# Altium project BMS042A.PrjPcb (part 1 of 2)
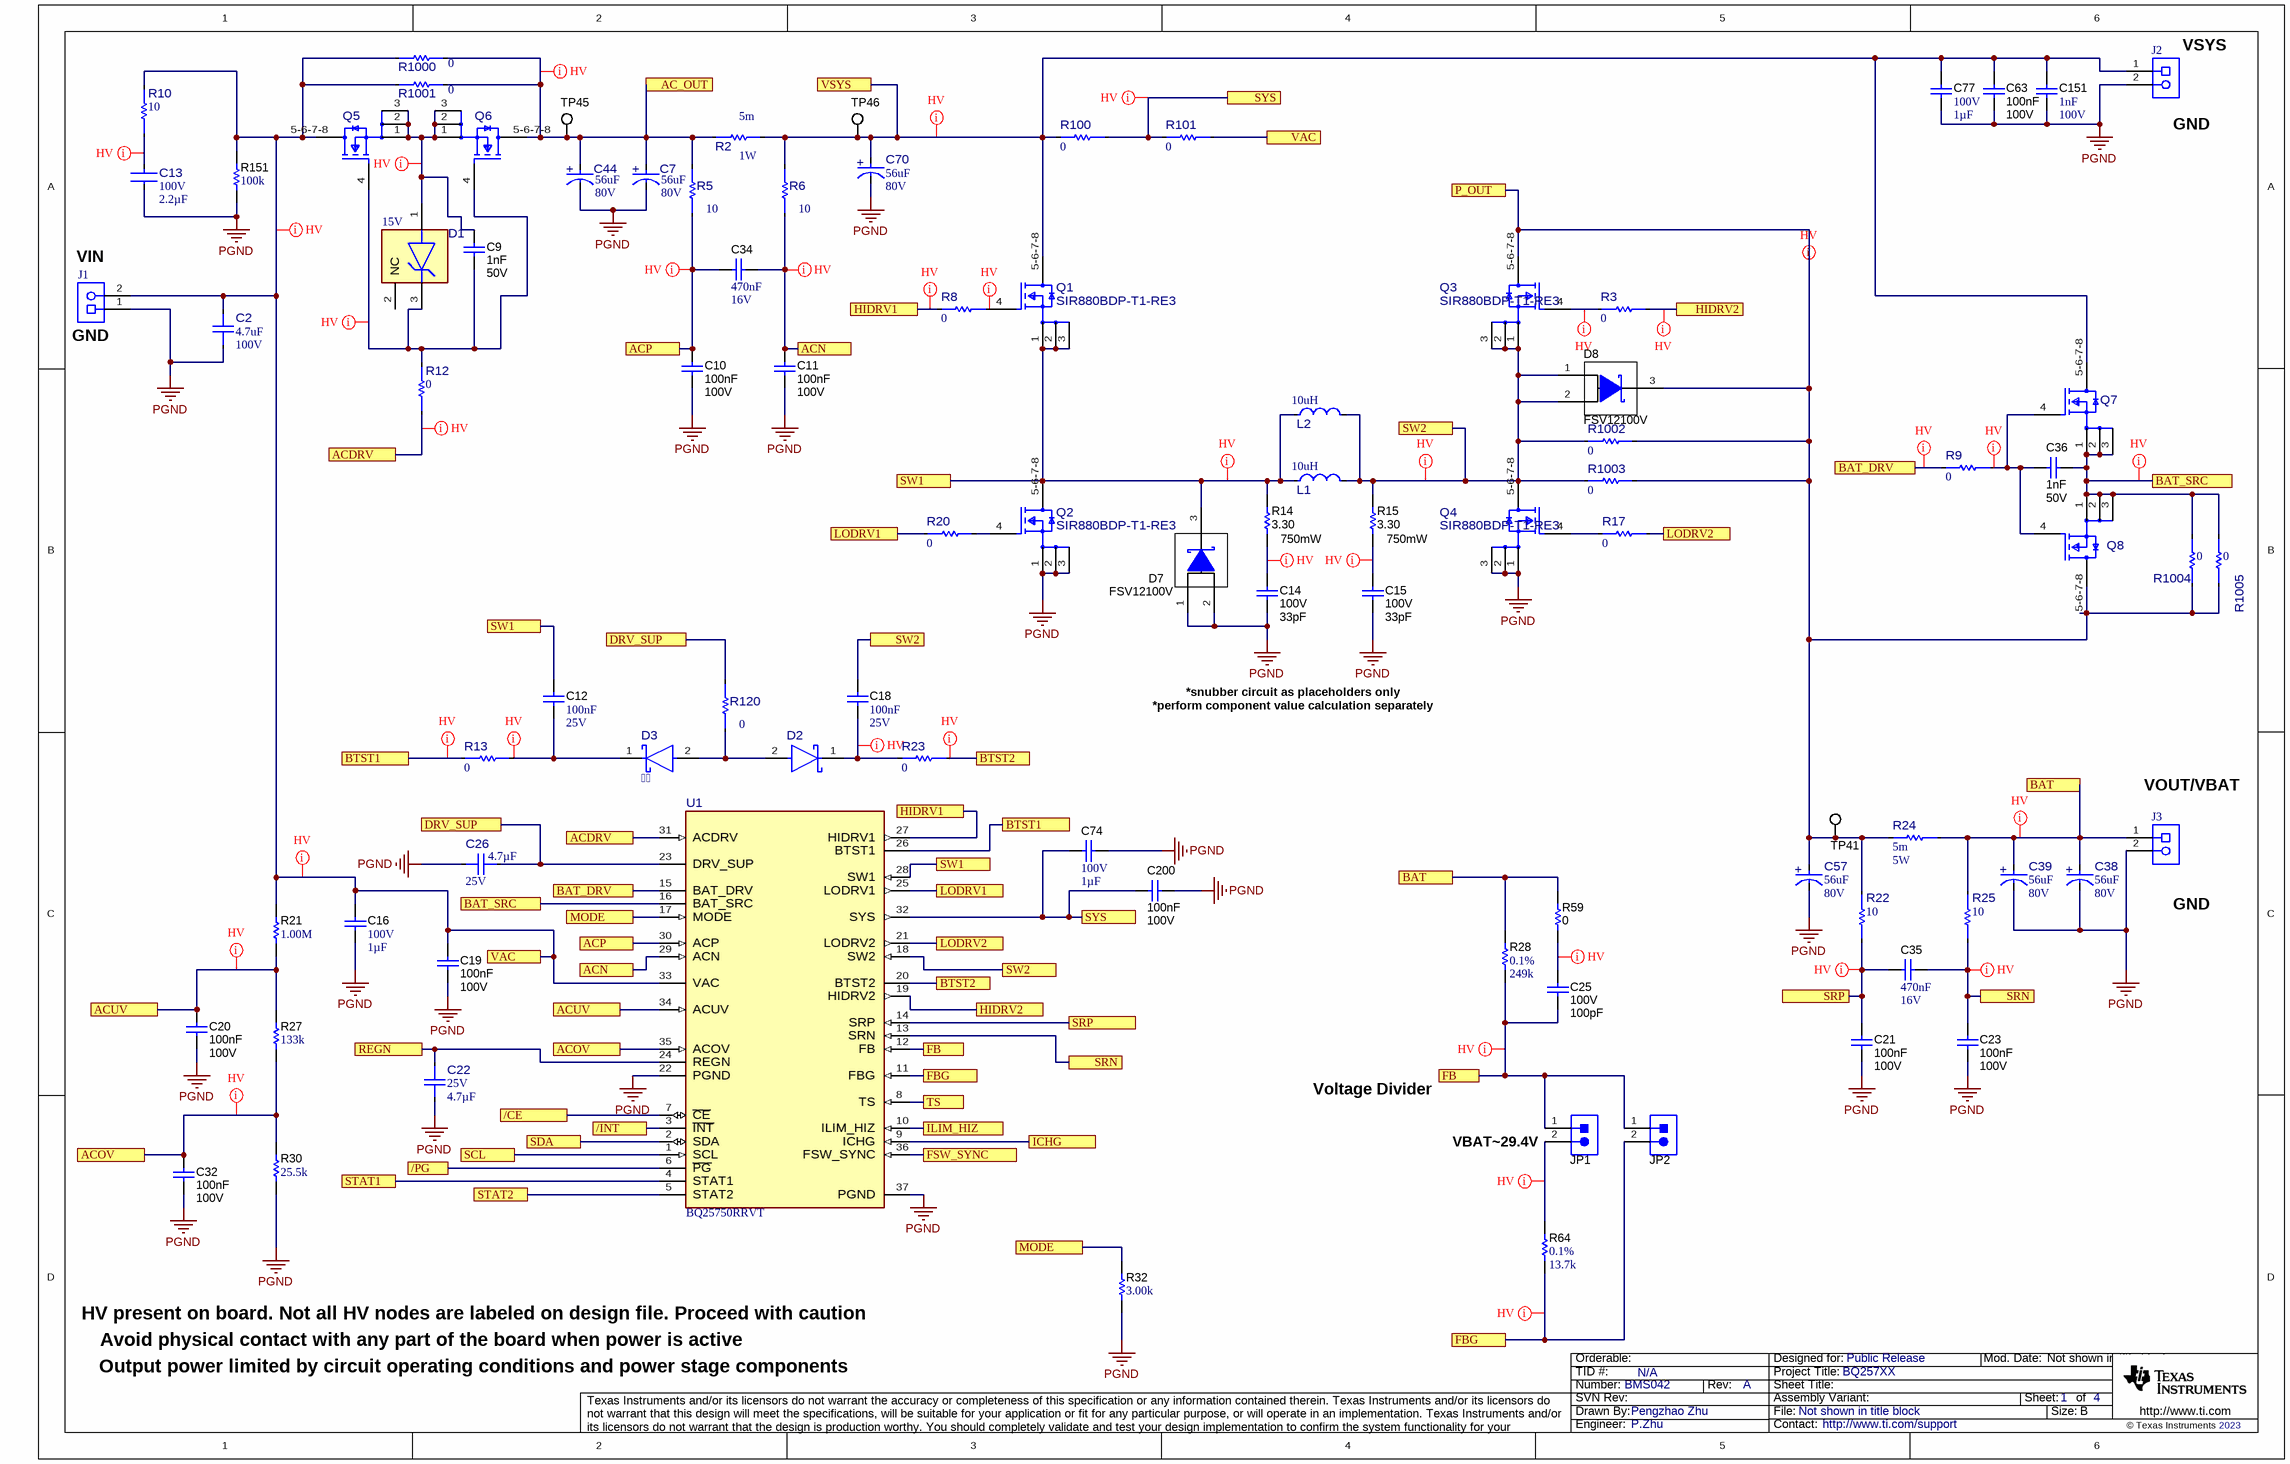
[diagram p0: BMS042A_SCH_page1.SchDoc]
CopyrightYear: 2023; DrawnBy: Pengzhao Zhu; PCB_Layout: P.Zhu; PCB_Rev: A; PRJ_Customer: Public Release; PRJ_Engineer: P.Zhu; PRJ_Number: BMS042; PRJ_Title: BQ257XX; SCH_Rev: A; TechSupport: http://www.ti.com/support; TID: N/A
4 sheets, 274 parts. Net scope: flat (ports and power ports of the same name join across sheets).
Board file: BMS042A_PCB.PcbDoc
Sheets:
  BMS042A_SCH_page1.SchDoc
  BMS042A_SCH_page2.SchDoc
  BMS042A_SCH_powerpath_capacitors.SchDoc
  BMS042A_SCH_Hardware.SchDoc

## Sheet BMS042A_SCH_page1.SchDoc
size 431 x 279 mm; Date: Not shown in title block; ApprovedBy: Not shown in title block; CheckedBy: Not shown in title block; Author: Not shown in title block; CompanyName: Not shown in title block; DrawnBy: Pengzhao Zhu; Engineer: Not shown in title block; Organization: Not shown in title block; Address1: Not shown in title block; Address2: Not shown in title block; Address3: Not shown in title block; Address4: Not shown in title block; DocumentNumber: 1; Revision: Use project parameter SCH_Rev; SheetNumber: 1; SheetTotal: 4; PageSetup: Record=PageOptions¦CenterHorizontal=True¦CenterVertical=True¦PrintScale=1.00¦XCorrection=1.00¦YCorrection=1.00¦PrintKind=0¦BorderSize=5000000¦LeftOffset=0¦BottomOffset=0¦Orientation=2¦PaperLength=1000¦PaperWidth=1000¦Scale=100¦PaperSource=15¦PrintQuality=600¦MediaType=1¦DitherType=10¦PaperKind=Letter¦PrintScaleMode=1

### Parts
C2  ValueDisplayed: 4.7uF  VDC_V: 100V  [FP-GCJ32DC72A475KE01L_1210-MFG]  (hidden comment: GCJ32DC72A475KE01L)
C7  ValueDisplayed: 56uF  VDC_V: 80V  [FP-80SXV56M_SMT_CAP_10MM3_10MM3-MFG]  (hidden comment: 80SXV56M)
C9  Cap_F: 1nF  VDC_V: 50V  [0603_HV]  (hidden comment: C0603C102J5RACTU)
C10  Cap_F: 100nF  VDC_V: 100V  [0603_HV]  (hidden comment: HMK107B7104KAHT)
C11  Cap_F: 100nF  VDC_V: 100V  [0603_HV]  (hidden comment: HMK107B7104KAHT)
C12  Cap_F: 100nF  VDC_V: 25V  [0603_HV]  (hidden comment: 06033C104KAT2A)
C13  VDC_V: 100V  Cap_F: 2.2µF  [FP-CGA6N3X7R2A225K230AE_1210-MFG]  (hidden comment: CGA6N3X7R2A225K230AE)
C14  VDC_V: 100V  ValueDisplayed: 33pF  [0603_HV]  (hidden comment: 06031A330JAT2A)
C15  VDC_V: 100V  ValueDisplayed: 33pF  [0603_HV]  (hidden comment: 06031A330JAT2A)
C16  VDC_V: 100V  Cap_F: 1µF  [0805_150]  (hidden comment: 08051C105K4Z2A)
C18  Cap_F: 100nF  VDC_V: 25V  [0603_HV]  (hidden comment: 06033C104KAT2A)
C19  Cap_F: 100nF  VDC_V: 100V  [0603_HV]  (hidden comment: HMK107B7104KAHT)
C20  Cap_F: 100nF  VDC_V: 100V  [0603_HV]  (hidden comment: HMK107B7104KAHT)
C21  Cap_F: 100nF  VDC_V: 100V  [0603_HV]  (hidden comment: HMK107B7104KAHT)
C22  VDC_V: 25V  Cap_F: 4.7µF  [FP-CGA4J1X7R1E475K125AE_0805-MFG]  (hidden comment: CGA4J1X7R1E475K125AE)
C23  Cap_F: 100nF  VDC_V: 100V  [0603_HV]  (hidden comment: HMK107B7104KAHT)
C25  VDC_V: 100V  ValueDisplayed: 100pF  [0603_HV]  (hidden comment: GCM1885C2A101JA16D)
C26  VDC_V: 25V  Cap_F: 4.7µF  [FP-CGA4J1X7R1E475K125AE_0805-MFG]  (hidden comment: CGA4J1X7R1E475K125AE)
C32  Cap_F: 100nF  VDC_V: 100V  [0603_HV]  (hidden comment: HMK107B7104KAHT)
C34  Cap_F: 470nF  VDC_V: 16V  [0603]  (hidden comment: C0603C474K4RACTU)
C35  Cap_F: 470nF  VDC_V: 16V  [0603]  (hidden comment: C0603C474K4RACTU)
C36  Cap_F: 1nF  VDC_V: 50V  [0603_HV]  (hidden comment: C0603C102J5RACTU)
C38  ValueDisplayed: 56uF  VDC_V: 80V  [FP-80SXV56M_SMT_CAP_10MM3_10MM3-MFG]  (hidden comment: 80SXV56M)
C39  ValueDisplayed: 56uF  VDC_V: 80V  [FP-80SXV56M_SMT_CAP_10MM3_10MM3-MFG]  (hidden comment: 80SXV56M)
C44  ValueDisplayed: 56uF  VDC_V: 80V  [FP-80SXV56M_SMT_CAP_10MM3_10MM3-MFG]  (hidden comment: 80SXV56M)
C57  ValueDisplayed: 56uF  VDC_V: 80V  [FP-80SXV56M_SMT_CAP_10MM3_10MM3-MFG]  (hidden comment: 80SXV56M)
C63  Cap_F: 100nF  VDC_V: 100V  [0603L]  (hidden comment: HMK107B7104KAHT)
C70  ValueDisplayed: 56uF  VDC_V: 80V  [FP-80SXV56M_SMT_CAP_10MM3_10MM3-MFG]  (hidden comment: 80SXV56M)
C74  VDC_V: 100V  Cap_F: 1µF  [0805_150]  (hidden comment: 08051C105K4Z2A)
C77  VDC_V: 100V  Cap_F: 1µF  [0805_150]  (hidden comment: 08051C105K4Z2A)
C151  Cap_F: 1nF  VDC_V: 100V  [0603]  (hidden comment: CGA3E2X7R2A102K080AA)
C200  Cap_F: 100nF  VDC_V: 100V  [0603_HV]  (hidden comment: HMK107B7104KAHT)
D1  Vz_V: 15V  [FP-SZBZX84C15LT3G_SOT23-MFG]
D2  (no value)  [FP-V1FM10-M3-H_DO-219AB-MFG]
D3    [FP-V1FM10-M3-H_DO-219AB-MFG]
D7  FSV12100V  [TO-277A]
D8  FSV12100V  [TO-277A]
J1  (no value)  [FP-TB005-762-02BE_TERM_CONN-MFG]
J2  (no value)  [FP-TB005-762-02BE_TERM_CONN-MFG]
J3  (no value)  [FP-TB005-762-02BE_TERM_CONN-MFG]
JP1  PEC02SAAN  [CONN_PEC02SAAN]  (value not drawn)
JP2  PEC02SAAN  [CONN_PEC02SAAN]  (value not drawn)
L1  value 10uH  [FP-IHLP6767GZER100M01_SMT_INDUCTOR_17MM15_17MM15-MFG]  (hidden comment: IHLP6767GZER100M01)
L2  value 10uH  [FP-CMLB135T-100MS_SMT2_13MM45_12Mm6-MFG]  (hidden comment: CMLB135T-100MS)
Q1  SIR880BDP-T1-RE3  [FP-SIR880BDP-T1-RE3_SO-8-MFG]
Q2  SIR880BDP-T1-RE3  [FP-SIR880BDP-T1-RE3_SO-8-MFG]
Q3  SIR880BDP-T1-RE3  [FP-SIR880BDP-T1-RE3_SO-8-MFG]
Q4  SIR880BDP-T1-RE3  [FP-SIR880BDP-T1-RE3_SO-8-MFG]
Q5  (no value)  [FP-AONS66917_DFN8-MFG]
Q6  (no value)  [FP-AONS66917_DFN8-MFG]
Q7  (no value)  [FP-AONS66917_DFN8-MFG]
Q8  (no value)  [FP-AONS66917_DFN8-MFG]
R2  Res_ohm: 5m  Power_W: 1W  [FP-WSL25125L000FEA_2512-MFG]  (hidden comment: WSL25125L000FEA)
R3  value 0  [FP-CRCW06031R50FKEAHP_0603-MFG]  (hidden comment: CRCW06030000Z0EA)
R5  value 10  [FP-CRCW060310R0FKEB_0603-MFG]  (hidden comment: CRCW060310R0FKEB)
R6  value 10  [FP-CRCW060310R0FKEB_0603-MFG]  (hidden comment: CRCW060310R0FKEB)
R8  value 0  [FP-CRCW06031R50FKEAHP_0603-MFG]  (hidden comment: CRCW06030000Z0EA)
R9  value 0  [FP-CRCW06031R50FKEAHP_0603-MFG]  (hidden comment: CRCW06030000Z0EA)
R10  value 10  [FP-CRCW120610R0FKEAHP_1206-MFG]  (hidden comment: CRCW120610R0FKEAHP)
R12  value 0  [FP-CRCW06031R50FKEAHP_0603-MFG]  (hidden comment: CRCW06030000Z0EA)
R13  value 0  [FP-CRCW06031R50FKEAHP_0603-MFG]  (hidden comment: CRCW06030000Z0EA)
R14  Power_W: 750mW  ValueDisplayed: 3.30  [1210]  (hidden comment: CRCW12103R30FKEAHP)
R15  Power_W: 750mW  ValueDisplayed: 3.30  [1210]  (hidden comment: CRCW12103R30FKEAHP)
R17  value 0  [FP-CRCW06031R50FKEAHP_0603-MFG]  (hidden comment: CRCW06030000Z0EA)
R20  value 0  [FP-CRCW06031R50FKEAHP_0603-MFG]  (hidden comment: CRCW06030000Z0EA)
R21  ValueDisplayed: 1.00M  [0805_HV]  (hidden comment: CRCW08051M00FKEAC)
R22  value 10  [FP-CRCW060310R0FKEB_0603-MFG]  (hidden comment: CRCW060310R0FKEB)
R23  value 0  [FP-CRCW06031R50FKEAHP_0603-MFG]  (hidden comment: CRCW06030000Z0EA)
R24  value 5m  Power_W: 5W  [FP-FCSL110R005FER_WIDE_4320-MFG]  (hidden comment: FCSL110R005FER)
R25  value 10  [FP-CRCW060310R0FKEB_0603-MFG]  (hidden comment: CRCW060310R0FKEB)
R27  ValueDisplayed: 133k  [0805_HV]  (hidden comment: ERJ-6ENF1333V)
R28  Value1: 0.1%  ValueDisplayed: 249k  [0805_HV]  (hidden comment: ERJ-PB6B2493V)
R30  ValueDisplayed: 25.5k  [0805_HV]  (hidden comment: ERJ-6ENF2552V)
R32  ValueDisplayed: 3.00k  [0805_HV]  (hidden comment: ERJ-6ENF3001V)
R59  ValueDisplayed: 0  [0805_HV]  (hidden comment: RC0805JR-070RL)
R64  Tolerance_%: 0.1%  ValueDisplayed: 13.7k  [0805_HV]  (hidden comment: RG2012P-1372-B-T5)
R100  value 0  [FP-CRCW06031R50FKEAHP_0603-MFG]  (hidden comment: CRCW06030000Z0EA)
R101  value 0  [FP-CRCW06031R50FKEAHP_0603-MFG]  (hidden comment: CRCW06030000Z0EA)
R120  value 0  [FP-CRCW080510R0JNEAHP_0805-MFG]  (hidden comment: CRCW08050000Z0EA)
R151  ValueDisplayed: 100k  [1210]  (hidden comment: RC1210JR-07100KL)
R1000  value 0  [FP-JR0805X35E_0805-MFG]  (hidden comment: JR0805X35E)
R1001  value 0  [FP-JR0805X35E_0805-MFG]  (hidden comment: JR0805X35E)
R1002  value 0  [FP-JR0805X35E_0805-MFG]  (hidden comment: JR0805X35E)
R1003  value 0  [FP-JR0805X35E_0805-MFG]  (hidden comment: JR0805X35E)
R1004  value 0  [FP-JR0805X35E_0805-MFG]  (hidden comment: JR0805X35E)
R1005  value 0  [FP-JR0805X35E_0805-MFG]  (hidden comment: JR0805X35E)
TP41  5002  [Keystone5002]  (value not drawn)
TP45  5002  [Keystone5002]  (value not drawn)
TP46  5002  [Keystone5002]  (value not drawn)
U1  BQ25750RRVT  [RRV0036A-MFG]

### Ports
/CE, /INT, /PG, AC_OUT, ACDRV, ACN, ACOV, ACP, ACUV, BAT, BAT_DRV, BAT_SRC, BTST1, BTST2, DRV_SUP, FB, FBG, FSW_SYNC, HIDRV1, HIDRV2, ICHG, ILIM_HIZ, LODRV1, LODRV2, MODE, P_OUT, REGN, SCL, SDA, SRN, SRP, STAT1, STAT2, SW1, SW2, SYS, TS, VAC, VSYS

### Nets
PGND: C2.1 C7.1(CATHODE) C10.2 C11.2 C13.2 C14.2 C15.2 C16.2 C19.2 C20.2 C21.2 C22.2 C23.2 C26.2 C32.2 C38.1(CATHODE) C39.1(CATHODE) C44.1(CATHODE) C57.1(CATHODE) C63.2 C70.1(CATHODE) C74.2 C77.2 C151.2 C200.2 D7.1(A) D7.2(A) J1.1 J2.2 J3.2 Q2.1(S) Q2.2(S) Q2.3(S) Q4.1(S) Q4.2(S) Q4.3(S) R30.1 R32.1 R151.1 U1.22(PGND) U1.37(PGND)
/CE: U1.7(~{CE}) ; port /CE
/INT: U1.3(~{INT}) ; port /INT
/PG: U1.6(~{PG}) ; port /PG
AC_OUT: C7.2(ANODE) C44.2(ANODE) Q6.5-6-7-8(D) R2.1 R5.2 R1000.2 R1001.2 TP45.1 ; port AC_OUT
ACDRV: R12.1 U1.31(ACDRV) ; port ACDRV
ACN: C11.1 C34.2 R6.1 U1.29(ACN) ; port ACN
ACOV: C32.1 R27.1 R30.2 U1.35(ACOV) ; port ACOV
ACP: C10.1 C34.1 R5.1 U1.30(ACP) ; port ACP
ACUV: C20.1 R21.1 R27.2 U1.34(ACUV) ; port ACUV
BAT: C38.2(ANODE) C39.2(ANODE) J3.1 R24.1 R25.1 R28.2 R59.2 ; port BAT
BAT_DRV: R9.2 U1.15(BAT_DRV) ; port BAT_DRV
BAT_SRC: C36.2 Q7.1(S) Q7.2(S) Q7.3(S) Q8.1(S) Q8.2(S) Q8.3(S) R1004.2 R1005.2 U1.16(BAT_SRC) ; port BAT_SRC
BTST1: R13.1 U1.26(BTST1) ; port BTST1
BTST2: R23.1 U1.20(BTST2) ; port BTST2
DRV_SUP: C26.1 R120.2 U1.23(DRV_SUP) ; port DRV_SUP
FB: C25.2 JP1.1 JP2.1 R28.1 U1.12(FB) ; port FB
FBG: JP2.2 R64.1 U1.11(FBG) ; port FBG
FSW_SYNC: U1.36(FSW_SYNC) ; port FSW_SYNC
HIDRV1: R8.2 U1.27(HIDRV1) ; port HIDRV1
HIDRV2: R3.2 U1.19(HIDRV2) ; port HIDRV2
ICHG: U1.9(ICHG) ; port ICHG
ILIM_HIZ: U1.10(ILIM_HIZ) ; port ILIM_HIZ
LODRV1: R20.1 U1.25(LODRV1) ; port LODRV1
LODRV2: R17.1 U1.21(LODRV2) ; port LODRV2
MODE: R32.2 U1.17(MODE) ; port MODE
P_OUT: C57.2(ANODE) D8.3(K) Q3.5-6-7-8(D) Q8.5-6-7-8(D) R22.1 R24.2 R1002.2 R1003.2 R1004.1 R1005.1 TP41.1 ; port P_OUT
REGN: C22.1 U1.24(REGN) ; port REGN
SCL: U1.1(SCL) ; port SCL
SDA: U1.2(SDA) ; port SDA
SRN: C23.1 C35.2 R25.2 U1.13(SRN) ; port SRN
SRP: C21.1 C35.1 R22.2 U1.14(SRP) ; port SRP
STAT1: U1.4(STAT1) ; port STAT1
STAT2: U1.5(STAT2) ; port STAT2
SW1: C12.1 D7.3(K) L1.1 L2.1 Q1.1(S) Q1.2(S) Q1.3(S) Q2.5-6-7-8(D) R14.2 U1.28(SW1) ; port SW1
SW2: C18.2 D8.1(A) D8.2(A) L1.2 L2.2 Q3.1(S) Q3.2(S) Q3.3(S) Q4.5-6-7-8(D) R15.2 R1002.1 R1003.1 U1.18(SW2) ; port SW2
SYS: C74.1 C200.1 R100.1 R101.2 U1.32(SYS) ; port SYS
TS: U1.8(TS) ; port TS
VAC: C2.2 C16.1 C19.1 J1.2 Q5.5-6-7-8(D) R10.2 R21.2 R101.1 R151.2 R1000.1 R1001.1 U1.33(VAC) ; port VAC
VSYS: C63.1 C70.2(ANODE) C77.1 C151.1 J2.1 Q1.5-6-7-8(D) Q7.5-6-7-8(D) R2.2 R6.2 R100.2 TP46.1 ; port VSYS
NetC9_1: C9.1 D1.1(Anode) Q5.1(S) Q5.2(S) Q5.3(S) Q6.1(S) Q6.2(S) Q6.3(S)
NetC9_2: C9.2 D1.3(Cathode) Q5.4(G) Q6.4(G) R12.2
NetC12_2: C12.2 D3.1(CATHODE) R13.2
NetC13_1: C13.1 R10.1
NetC14_1: C14.1 R14.1
NetC15_1: C15.1 R15.1
NetC18_1: C18.1 D2.1(CATHODE) R23.2
NetC25_1: C25.1 R59.1
NetC36_1: C36.1 Q7.4(G) Q8.4(G) R9.1
NetD2_2: D2.2(ANODE) D3.2(ANODE) R120.1
NetJP1_2: JP1.2 R64.2
NetQ1_4: Q1.4(G) R8.1
NetQ2_4: Q2.4(G) R20.2
NetQ3_4: Q3.4(G) R3.1
NetQ4_4: Q4.4(G) R17.2

Not connected (* = marked no-connect by the designer): D1 2(NC)

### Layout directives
net class HV: AC_OUT, ACDRV, ACN, ACOV, ACP, ACUV, BAT, BAT_DRV, BAT_SRC, BTST1, BTST2, FB, FBG, HIDRV1, HIDRV2, NetC9_1, NetC9_2, NetC12_2, NetC13_1, NetC14_1, NetC15_1, NetC18_1, NetC25_1, NetC36_1, NetJP1_2, NetQ1_4, NetQ3_4, P_OUT, SRN, SRP, SW1, SW2, SYS, VAC, VSYS

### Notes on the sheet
- (near J2) VSYS
- (near J2) GND
- (near J1) VIN
- (near J1) GND
- *snubber circuit as placeholders only
- *perform component value calculation separately
- (near J3) VOUT/VBAT
- (near J3) GND
- Voltage Divider
- (near JP1) VBAT|9.4V
- Avoid physical contact with any part of the board when power is active
- HV present on board. Not all HV nodes are labeled on design file. Proceed with caution
- Output power limited by circuit operating conditions and power stage components

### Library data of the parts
C2 = CMP-0093675-1: 4.7uF ±10% 100V Ceramic Capacitor X7S 1210 (3225 Metric); Manufacturer: Murata; Value: 4.7µF; AEC Qualified: Yes; TempCo: 22%; SizeZ_mm: 2.3mm; AEC Grade: Grade 1
C7 C38 C39 C44 C57 C70 = CMP-0093756-1: 56 µF 80 V Aluminum - Polymer Capacitors Radial, Can - SMD 28mOhm 1000 Hrs @ 125°C; Manufacturer: Panasonic; Life: 1000Hours; Esr: 28m; IRMS_A: 3.1A; Leakage Current: 224uA; Tolerance_%: 20%; Cap_F: 56µF; AEC Qualified: No; Dissipation Factor: 12%; SizeZ_mm: 12.7mm; Value: 56µF
C9 C36 = CMP-0006845-4: CAP, CERM, 1000 pF, 50 V, +/- 5%, X7R, 0603; Manufacturer: Kemet; TaMin_C: -55°C; Polarized: N; SizeAreaWB_mm2: 4.68; Value1: Unknown; U/M: EA; Value: 1000pF; TaMax_C: 125°C; SizeZ_mm: 1; SizeX_mm: 1.6; SizeY_mm: 0.8; Cap_Case: 0603; SizeArea_mm2: 1.28; AEC Category: Q200
C10 C11 C19-C21 C23 C32 C63 C200 = CMP-0081011-1: CAP, CERM, 0.1 µF, 100 V,+/- 10%, X7R, AEC-Q200 Grade 1, 0603; Manufacturer: Taiyo Yuden; SizeAreaWB_mm2: 4.68; SizeArea_mm2: 1.28; AEC Qualified: Y; AEC Category: Q200; Value: 0.1uF; TaMax_C: 125°C; SizeZ_mm: 1; Polarized: N; TaMin_C: -55°C; SizeY_mm: 0.8; U/M: EA; SizeX_mm: 1.6; Cap_Case: 0603; ValueDisplayed: 0.1µF
C12 C18 = CMP-0006753-4: CAP, CERM, 0.1 uF, 25 V, +/- 10%, X7R, 0603; Manufacturer: AVX; TaMin_C: -55°C; ESR_ohm: 50m; Polarized: N; SizeAreaWB_mm2: 4.68; Value1: 0.05 ohm; U/M: EA; Value: 0.1uF; TaMax_C: 125°C; SizeZ_mm: 1; SizeX_mm: 1.6; SizeY_mm: 0.8; Cap_Case: 0603; SizeArea_mm2: 1.28; AEC Category: Q200
C13 = CMP-0087124-1: Cap Ceramic 2.2uF 100V X7R 10% SMD 1210 FlexiTerm 125C Plastic T/R; Manufacturer: TDK Corporation; TempCo: 15%; AEC Qualified: Yes; SizeZ_mm: 2.6mm; AEC Grade: Grade 1
C14 C15 = CMP-0006722-4: CAP, CERM, 33 pF, 100 V, +/- 5%, C0G/NP0, 0603; Manufacturer: AVX; TaMin_C: -55°C; ESR_ohm: 0.209; Polarized: N; SizeAreaWB_mm2: 4.68; Value1: 0.209 ohm; U/M: EA; Value: 33pF; TaMax_C: 125°C; SizeZ_mm: 1; SizeX_mm: 1.6; SizeY_mm: 0.8; Cap_Case: 0603; SizeArea_mm2: 1.28; AEC Category: Q200
C16 C74 C77 = CMP-0861070-1: CAP, CERM, 1 µF, 100 V,+/- 10%, X7R, AEC-Q200 Grade 1, 0805; Manufacturer: AVX; SizeZ_mm: 1.5; Polarized: N; TaMax_C: 125°C; TaMin_C: -55°C; Value: 1uF; AEC Qualified: Y; U/M: EA; AEC Grade: 1; Cap_Case: 0805; SizeX_mm: 2; SizeArea_mm2: 2.5; SizeAreaWB_mm2: 6.75; AEC Category: Q200; SizeY_mm: 1.25
C22 C26 = CMP-0093626-1: Cap Ceramic 4.7uF 25V X7R 10% Pad SMD 0805 +125°C Automotive T/R; Manufacturer: TDK Corporation; SizeZ_mm: 1.45mm; TempCo: 15%; AEC Qualified: Yes; Value: 4.7µF; Tolerance_%: 0.1%; AEC Grade: Grade 1
C25 = CMP-0007130-4: CAP, CERM, 100 pF, 100 V, +/- 5%, C0G/NP0, AEC-Q200 Grade 1, 0603; Manufacturer: MuRata; TaMin_C: -55°C; Polarized: N; SizeAreaWB_mm2: 4.68; Value1: Unknown; U/M: EA; TaMax_C: 125°C; SizeZ_mm: 1; SizeX_mm: 1.6; SizeY_mm: 0.8; Cap_Case: 0603; SizeArea_mm2: 1.28; AEC Qualified: Y; AEC Category: Q200; Value: 100pF
C34 C35 = CMP-0006944-4: CAP, CERM, 0.47 uF, 16 V, +/- 10%, X7R, 0603; Manufacturer: Kemet; TaMin_C: -55°C; Polarized: N; SizeAreaWB_mm2: 4.68; Value1: Unknown; U/M: EA; Value: 0.47uF; TaMax_C: 125°C; SizeZ_mm: 1; SizeX_mm: 1.6; SizeY_mm: 0.8; SizeArea_mm2: 1.28; AEC Category: Q200
C151 = CMP-0007081-4: Multilayer Ceramic Capacitors MLCC - SMD/SMT CGA 0603 100V 1000pF X7R 10% AEC-Q200; Manufacturer: TDK; TaMin_C: -55°C; ESR_ohm: 1.9714; Polarized: N; SizeAreaWB_mm2: 4.68; Value1: 1.97137 ohm; U/M: EA; TaMax_C: 125°C; SizeZ_mm: 1; SizeX_mm: 1.6; SizeY_mm: 0.8; SizeArea_mm2: 1.28; AEC Qualified: Y; IRMS_A: 305.705mA; AEC Category: Q200
D1 = CMP-0093134-1: Zener Diode Single 15V 5% 30Ohm 300mW Automotive 3-Pin SOT-23 T/R; Part Number: SZBZX84C15LT3G; Manufacturer: On Semiconductor; TJmax_C: +150°C; SizeZ_mm: 1.11mm; Power_W: 250mW; Ciiva Ids: 807354; VRWM: 15.6V; Vr_V: 10.5V; AEC Grade: Grade 0; Standoff Height: 0.01mm; Max Reverse Leakage Current: 0.05uA; Zener Impedance: 30Ω; Import Ts: 1521856680; AEC Qualified: Yes
D2 D3 = CMP-0093639-2: Diode Schottky 1A Surface Mount DO-219AB (SMF); Part Number: V1FM10-M3/H; Manufacturer: Vishay; Max Surge Forward Current: 30A; TJmax_C: 175°C; AEC Qualified: No; Cap_F: 95pF; AEC Category: Q101; Standoff Height: 0mm; SizeZ_mm: 1.08mm; Vr_V: 100V; Peak Reverse Current: 0.2uA
D7 D8 = CMP-0028821-2: Diode, Schottky, 100 V, 12 A, AEC-Q101, TO-277A; Manufacturer: Fairchild Semiconductor; TJmax_C: 150°C; Green_Lifecycle: Not Set; Vr_V: 100V; Value: 100V; SizeY_mm: 4.75; Vf_V: 670mV; Green_REACh: Incomplete; SizeAreaWB_mm2: 57.375; SizeX_mm: 6.5; SizeArea_mm2: 30.875; Value2: 0.67V; Io_A: 12A; AEC Qualified: Y; SizeZ_mm: 1.2; AEC Category: Q101
J1-J3 = CMP-0093294-2: PartNumber: TB005-762-02BE; Manufacturer: CUI Devices; Min Wire Gauge: 26; ContactFinish: Tin; Conn Gender: Female; Conn Orientation: Horizontal; DUT-Pitch_mm: 7.62mm; AEC Qualified: No; Row_Count: 1; SizeZ_mm: 22.1mm; Max Wire Gauge: 10; Voltage_V: 300V; Current_A: 30A; Is Female: yes
JP1 JP2 = CMP-0002337-1: Header, 100mil, 2x1, Tin, TH; Manufacturer: Sullins Connector Solutions; Cert_UL: Y; CNHeader: TRUE; CT: FALSE; Current_A: 3A; Gender: Male; Green_Lifecycle: Not Set; Green_REACh: Incomplete; Pitch_mm: 2.54; Row_Count: 1; Shrouded: N; Voltage_V: 1.8kV
L1 = CMP-0093259-1: Commercial Inductors, High Saturation Series 10uH 16.5A 12mΩ 20%; Manufacturer: Vishay; Material: SMC; SizeZ_mm: 7mm; Shrouded: true; Isat: 25A; DCR_ohm: 12m; Test Frequency: 100kHz; AEC Qualified: No; Ind_H: 10µH
L2 = CMP-0096007-1: Power Choke Coil 10uH 20% 9A 22mOhm; Manufacturer: Cyntec; Material: Metal Dust; SizeZ_mm: 5mm; Standoff Height: 0mm; Ind_H: 10µH; AEC Qualified: No; Isat: 10.5A; Test Frequency: 100kHz; DCR_ohm: 22m
Q1-Q4 = CMP-0096839-1: N-Channel 80 V 18.6A (Ta), 70.6A (Tc) 5W (Ta), 71.4W (Tc) Surface Mount PowerPAK® SO-8; Manufacturer: Vishay; QgTyp_nC: 43.5nC @ 10V; Turn On Delay Time: 12ns; Rthja Max: 20°C/W; Turn Off Delay Time: 40ns; Reverse Recovery Charge: 52nC; Typ Forward Diode Voltage: 0.74V; VdsMax_V: 1.1V; SizeZ_mm: 1.12mm; Number Of Channels: 1; Pulse Drain Current: 200A; Threshold Vgs Min: 1V; TJmax_C: +150°C; AEC Qualified: No; Transconductance: 49S; ChMode: False; Reverse Recovery Time: 38ns; Threshold Vgs Max: 2.4V; Input Capacitace At Vds: 2930pF @ 40V; Vgs_V: 20V; Drain To Source Breakdown Voltage: 80V; Rdson45_ohm: 5.3m
Q5-Q8 = CMP-0093242-3: 100V N-Channel MOSFET, DFN5x6-8L, RoHS; Part Number: AONS66917; Manufacturer: Alpha & Omega Semiconductor; Threshold Vgs Max: 2.8V; Vgs_V: 20V; QgTyp_nC: 80nC @ 10V; AEC Qualified: No; Power_W: 6.2W; Number Of N Channels: 1; TJmax_C: +150°C; Reverse Recovery Time: 43ns; Threshold Vgs Min: 1.7V; Turn Off Delay Time: 46ns; Standoff Height: 0mm; Input Capacitace At Vds: 5940pF @ 50V; Pulse Drain Current: 320A; Reverse Recovery Charge: 208nC; Rdson45_ohm: 2.9m; IdsMax_A: 100A; Transconductance: 100S; ChMode: False; Turn On Delay Time: 16.5ns; VdsMax_V: 1V; SizeZ_mm: 1.05mm; Typ Forward Diode Voltage: 0.68V; Rthja Max: 40°C/W
R2 = CMP-0096841-1: Res Metal Strip 2512 0.005 Ohm 1% 1W 110ppm/C Molded SMD SMD Embossed Plastic T/R; Manufacturer: Vishay; TempCo: 110ppm/°C; AEC Grade: Grade 0; AEC Qualified: Yes; Category 5A00970A6D5C81C7: Uncategorized; Value: 5m; Category 5C6A91606D4187Ad: Resistors; Category Cd01000Bfc2916C6: Single Components; Category 7542B8484461Ae85: Passive Components; SizeZ_mm: 0.889mm
R3 R8 R9 R12 R13 R17 R20 R23 R100 R101 = CMP-0093629-1: Thick Film Resistors - SMD 1/10watt ZEROohm Jumper; Manufacturer: Vishay; AEC Grade: Grade 0; TempCo: 100ppm/°C; Power: 250mW; Res_ohm: 1.5; Power_W: 330mW; AEC Qualified: Yes; VDC_V: 75V; SizeZ_mm: 0.55mm; Tolerance_%: 1%
R5 R6 R22 R25 = CMP-0093685-1: RES Thick Film, 10Ω, 1%, 0.1W, 100ppm/°C, 0603; Manufacturer: Vishay; Approved Alternate Part Number: 541-1.00HHCT-ND; Power_W: 100mW; Voltage: 75V; SizeZ_mm: 0.5mm; AEC Grade: Grade 0; AEC Qualified: Yes
R10 = CMP-0093410-1: RES Thick Film, 10Ω, 1%, 0.75W, 100ppm/°C, 1206; Manufacturer: Vishay Dale; AEC Qualified: Yes; VDC_V: 200V; SizeZ_mm: 0.65mm; AEC Grade: Grade 0; Power_W: 750mW
R14 R15 = CMP-0015022-3: RES, 3.30, 1%, 0.75 W, AEC-Q200 Grade 0, 1210; Manufacturer: Vishay-Dale; TempCo: 100 ppm/C; SizeAreaWB_mm2: 14.7; Value_Code: 3R30; Value: 3.30; Res_ohm: 3.3; SizeX_mm: 3.2; SizeY_mm: 2.5; SizeZ_mm: 1.35; Value2: 0.75W; SizeArea_mm2: 8; AEC Qualified: Y; AEC Grade: 0; AEC Category: Q200
R21 = CMP-0021522-3: Thick Film Resistors - SMD 1/8Watt 1Mohms 1% Commercial Use; Manufacturer: Vishay / Dale; Power_W: 125mW; TempCo: 100 ppm/C; Value_Code: 1M00; Value: 1.00Meg; EIA_Code: E96; Res_ohm: 1M; SizeX_mm: 2; SizeY_mm: 1.25; SizeZ_mm: 1.45; Value2: 0.125W; SizeArea_mm2: 2.5; AEC Qualified: Y; AEC Category: Q200; AEC Grade: 0; SizeAreaWB_mm2: 6.75
R24 = CMP-0093177-1: 5 mOhms ±1% 5W Chip Resistor Wide 4320 (11050 Metric), 2043 Current Sense, Moisture Resistant Metal Foil; Manufacturer: Ohmite; AEC Qualified: No; TempCo: 50ppm/°C; SizeZ_mm: 0.7mm
R27 = CMP-0021561-3: RES, 133 k, 1%, 0.125 W, AEC-Q200 Grade 0, 0805; Manufacturer: Panasonic; Power_W: 125mW; TempCo: 100 ppm/C; Value: 133k; EIA_Code: E96; SizeX_mm: 2; SizeY_mm: 1.25; SizeZ_mm: 1.45; Value2: 0.125W; SizeArea_mm2: 2.5; AEC Qualified: Y; AEC Category: Q200; AEC Grade: 0; SizeAreaWB_mm2: 6.75
R28 = CMP-0018933-2: Thick Film Resistors - SMD 0805 Anti-Surge Res. 0.1%, 249Kohm; Manufacturer: Panasonic; Power_W: 125mW; TempCo: 25 ppm/C; U/M: EA; Value: 249k; EIA_Code: E192; SizeX_mm: 2; SizeY_mm: 1.25; SizeZ_mm: 1.45; Value2: 0.125W; SizeArea_mm2: 2.5; VDC_V: 100V; AEC Category: Q200
R30 = CMP-0021646-3: RES, 25.5 k, 1%, 0.125 W, AEC-Q200 Grade 0, 0805; Manufacturer: Panasonic; Power_W: 125mW; TempCo: 100 ppm/C; Value_Code: 25k5; Value: 25.5k; EIA_Code: E96; SizeX_mm: 2; SizeY_mm: 1.25; SizeZ_mm: 1.45; Value2: 0.125W; SizeArea_mm2: 2.5; AEC Qualified: Y; AEC Category: Q200; AEC Grade: 0; SizeAreaWB_mm2: 6.75
R32 = CMP-0021666-2: RES, 3.00 k, 1%, 0.125 W, AEC-Q200 Grade 0, 0805; Manufacturer: Panasonic; Power_W: 125mW; TempCo: 100 ppm/C; Value_Code: 3k00; U/M: EA; Value: 3.00k; Res_ohm: 3k; SizeX_mm: 2; SizeY_mm: 1.25; SizeZ_mm: 1.45; Value2: 0.125W; SizeArea_mm2: 2.5; AEC Qualified: Y; VDC_V: 150V; AEC Grade: 0; AEC Category: Q200
R59 = CMP-0020803-2: RES, 0, 5%, 0.125 W, 0805; Manufacturer: Yageo America; Power_W: 125mW; TempCo: 200 ppm/C; Value_Code: 0000; U/M: EA; Value: 0; EIA_Code: E24; SizeX_mm: 2; SizeY_mm: 1.25; SizeZ_mm: 1.45; Value2: 0.125W; SizeArea_mm2: 2.5; VDC_V: 150V; AEC Category: Q200
R64 = CMP-0018881-2: RES, 13.7 k, 0.1%, 0.125 W, 0805; Manufacturer: Susumu Co Ltd; Power_W: 125mW; TempCo: 25 ppm/C; Value_Code: 13k7; U/M: EA; Value: 13.7k; EIA_Code: E192; SizeX_mm: 2; SizeY_mm: 1.25; SizeZ_mm: 1.45; Value2: 0.125W; SizeArea_mm2: 2.5; VDC_V: 100V; AEC Category: Q200
R120 = CMP-0092857-1: Thick Film Resistors - SMD 1/8watt ZEROohm Jumper; Manufacturer: Vishay; Power_W: 500mW; SizeZ_mm: 0.6mm; AEC Qualified: Yes; TempCo: 200ppm/°C; VDC_V: 150V; Tolerance_%: 5%; AEC Grade: Grade 0
R151 = CMP-0083440-1: RES, 100 k, 5%, 0.5 W, 1210; Manufacturer: Yageo; Power_W: 500mW; TempCo: 100 ppm/C; SizeAreaWB_mm2: 14.7; Value: 100k; EIA_Code: E24; SizeX_mm: 3.2; SizeY_mm: 2.5; SizeZ_mm: 1.35; Value2: 0.5W; SizeArea_mm2: 8; AEC Qualified: N; VDC_V: 200V; AEC Category: Q200
R1000-R1005 = CMP-0096818-1: 0 Ohms Jumper 0.245W Chip Resistor 0805 (2012 Metric) - Metal Element; Manufacturer: Ohmite; AEC Qualified: No; Power_W: 245mW; SizeZ_mm: 0.55mm
TP41 TP45 TP46 = CMP-0055139-1: Test Point, Miniature, White, TH; Manufacturer: Keystone; CNHeader: FALSE; ContactFinish: Silver; CT: TRUE; Green_Lifecycle: Active; Green_REACh: Passed
U1 = CMP-0091286-5: Standalone/I2C Controlled, 70V, 20A Buck-Boost Multi-Chemistry Battery Charge Controller; Manufacturer: Texas Instruments; Number Of Cells: 16; AEC Qualified: No; Number Of Outputs: 1; SizeZ_mm: 1mm; TJmax_C: +125°C; AEC Category: Q200; CompType: IC; Min Supply Voltage: 4.2V; TaMin_C: -40°C; Standoff Height: 0mm; Output Voltage: 0-60V; TaMax_C: +105°C

## Sheet BMS042A_SCH_page2.SchDoc: Headers
size 431 x 279 mm; Date: Not shown in title block; ApprovedBy: Not shown in title block; CheckedBy: Not shown in title block; Author: Not shown in title block; CompanyName: Not shown in title block; DrawnBy: Pengzhao Zhu; Engineer: Not shown in title block; Organization: Not shown in title block; Address1: Not shown in title block; Address2: Not shown in title block; Address3: Not shown in title block; Address4: Not shown in title block; DocumentNumber: 3; Revision: Use project parameter SCH_Rev; SheetNumber: 3; SheetTotal: 4; PageSetup: Record=PageOptions¦CenterHorizontal=True¦CenterVertical=True¦PrintScale=1.00¦XCorrection=1.00¦YCorrection=1.00¦PrintKind=0¦BorderSize=5000000¦LeftOffset=0¦BottomOffset=0¦Orientation=2¦PaperLength=1000¦PaperWidth=1000¦Scale=100¦PaperSource=15¦PrintQuality=600¦MediaType=1¦DitherType=10¦PaperKind=Letter¦PrintScaleMode=1
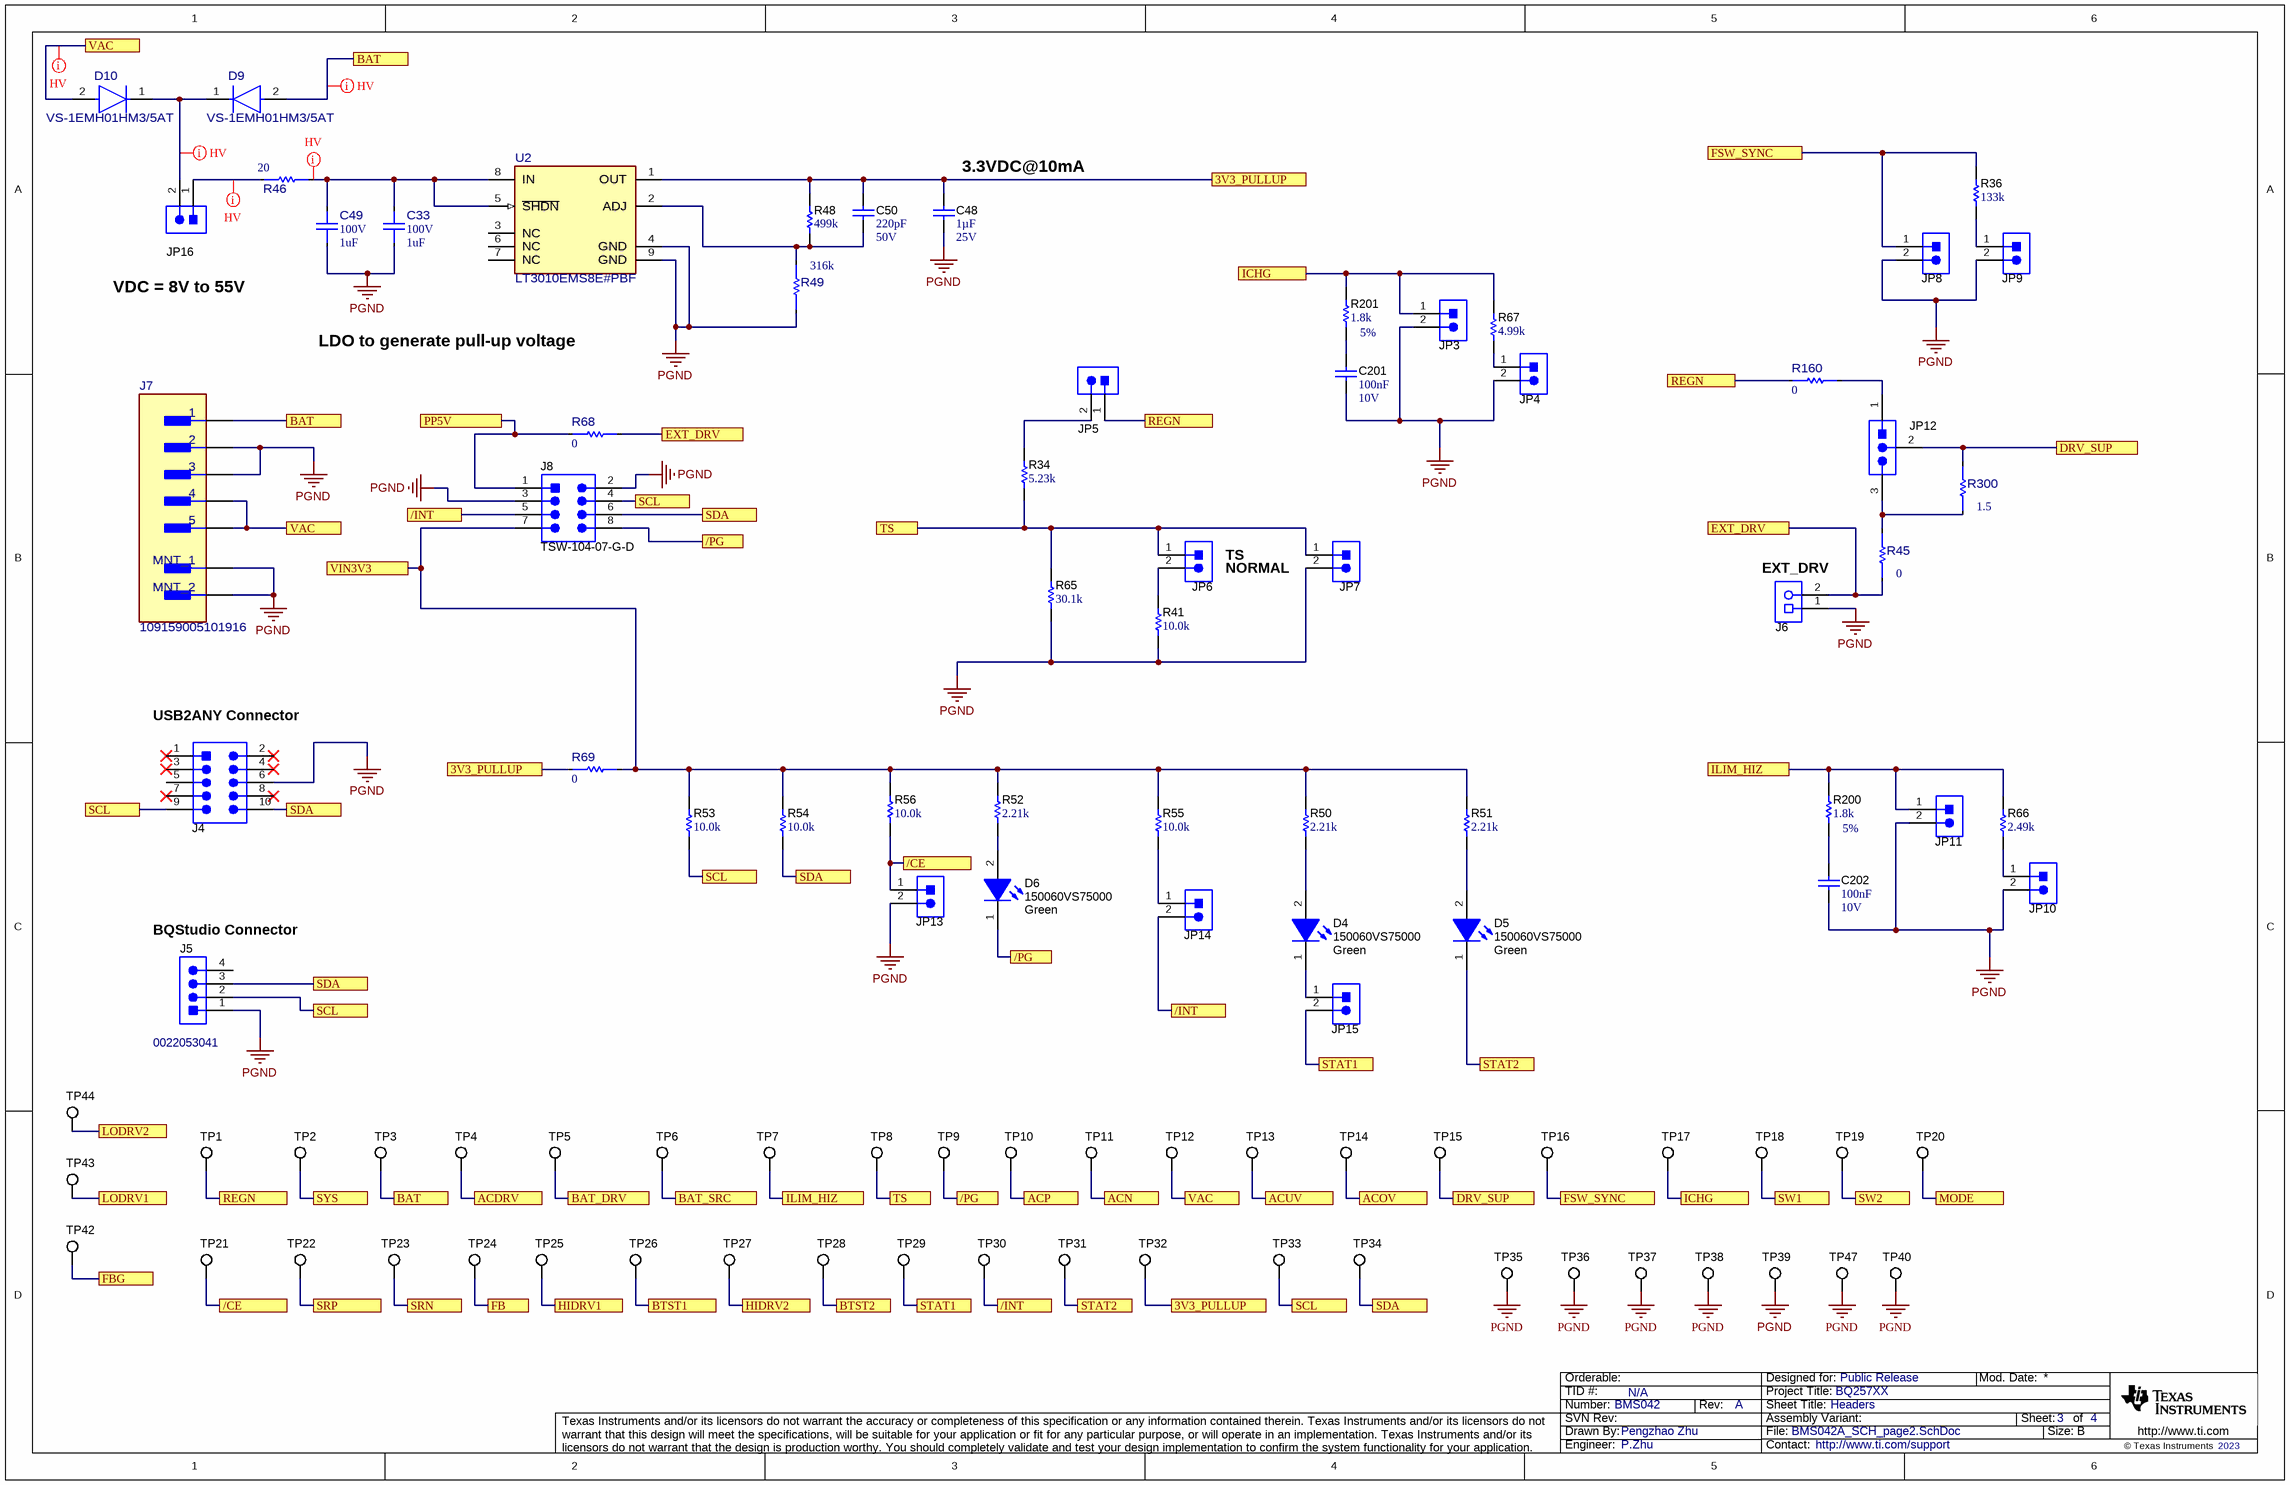
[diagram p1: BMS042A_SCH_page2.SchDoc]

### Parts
C33  VDC_V: 100V  ValueDisplayed: 1uF  [FP-12101C105KAT2A_1210-MFG]  (hidden comment: 12101C105KAT2A)
C48  Cap_F: 1µF  VDC_V: 25V  [0805_HV]  (hidden comment: C0805C105K3RACTU)
C49  VDC_V: 100V  ValueDisplayed: 1uF  [FP-12101C105KAT2A_1210-MFG]  (hidden comment: 12101C105KAT2A)
C50  Cap_F: 220pF  VDC_V: 50V  [0603]  (hidden comment: C0603C221K5RACTU)
C201  Cap_F: 100nF  VDC_V: 10V  [0603]  (hidden comment: C0603C104K8RACTU)
C202  Cap_F: 100nF  VDC_V: 10V  [0603]  (hidden comment: C0603C104K8RACTU)
D4  150060VS75000  value Green  [WL-SMCW_GREEN]
D5  150060VS75000  value Green  [WL-SMCW_GREEN]
D6  150060VS75000  value Green  [WL-SMCW_GREEN]
D9  VS-1EMH01HM3/5AT  [FP-VS-1EMH01HM3_5AT_DO-214AC-MFG]
D10  VS-1EMH01HM3/5AT  [FP-VS-1EMH01HM3_5AT_DO-214AC-MFG]
J4  N2510-6002-RB  [CONN_2510-6002]  (value not drawn)
J5  0022053041  [CONN_22-05-3041]
J6  0393570002  [MOLEX_39357-0002]  (value not drawn)
J7  109159005101916  [FP-109159005101916_CONN_SSL_PLUG5-MFG]
J8  TSW-104-07-G-D  [TSW-104-07-G-D]
JP3  Header_2x1  [CONN_PEC02SAAN]  (value not drawn)
JP4  Header_2x1  [CONN_PEC02SAAN]  (value not drawn)
JP5  Header_2x1  [CONN_PEC02SAAN]  (value not drawn)
JP6  Header_2x1  [CONN_PEC02SAAN]  (value not drawn)
JP7  Header_2x1  [CONN_PEC02SAAN]  (value not drawn)
JP8  Header_2x1  [CONN_PEC02SAAN]  (value not drawn)
JP9  Header_2x1  [CONN_PEC02SAAN]  (value not drawn)
JP10  Header_2x1  [CONN_PEC02SAAN]  (value not drawn)
JP11  Header_2x1  [CONN_PEC02SAAN]  (value not drawn)
JP12  PEC03SAAN  [CONN_PEC03SAAN]  (value not drawn)
JP13  PEC02SAAN  [CONN_PEC02SAAN]  (value not drawn)
JP14  PEC02SAAN  [CONN_PEC02SAAN]  (value not drawn)
JP15  PEC02SAAN  [CONN_PEC02SAAN]  (value not drawn)
JP16  Header_2x1  [CONN_PEC02SAAN]  (value not drawn)
R34  ValueDisplayed: 5.23k  [0603]  (hidden comment: RC0603FR-075K23L)
R36  ValueDisplayed: 133k  [0603]  (hidden comment: CRCW0603133KFKEA)
R41  ValueDisplayed: 10.0k  [0603]  (hidden comment: RC0603FR-0710KL)
R45  value 0  [FP-CRCW080510R0JNEAHP_0805-MFG]  (hidden comment: CRCW08050000Z0EA)
R46  value 20  [FP-CRCW12104R30FKEAHP_1210-MFG]  (hidden comment: CRCW121020R0FKEAHP)
R48  ValueDisplayed: 499k  [0603]  (hidden comment: RC0603FR-07499KL)
R49  value 316k  [FP-CR0603-FX-3163ELF_0603-MFG]  (hidden comment: CR0603-FX-3163ELF)
R50  ValueDisplayed: 2.21k  [0603]  (hidden comment: RC0603FR-072K21L)
R51  ValueDisplayed: 2.21k  [0603]  (hidden comment: RC0603FR-072K21L)
R52  ValueDisplayed: 2.21k  [0603]  (hidden comment: RC0603FR-072K21L)
R53  ValueDisplayed: 10.0k  [0603]  (hidden comment: RC0603FR-0710KL)
R54  ValueDisplayed: 10.0k  [0603]  (hidden comment: RC0603FR-0710KL)
R55  ValueDisplayed: 10.0k  [0603]  (hidden comment: RC0603FR-0710KL)
R56  ValueDisplayed: 10.0k  [0603]  (hidden comment: RC0603FR-0710KL)
R65  ValueDisplayed: 30.1k  [0603]  (hidden comment: RC0603FR-0730K1L)
R66  ValueDisplayed: 2.49k  [0603]  (hidden comment: RC0603FR-072K49L)
R67  ValueDisplayed: 4.99k  [0603]  (hidden comment: CRCW06034K99FKEAC)
R68  value 0  [FP-CRCW06031R50FKEAHP_0603-MFG]  (hidden comment: CRCW06030000Z0EA)
R69  value 0  [FP-CRCW06031R50FKEAHP_0603-MFG]  (hidden comment: CRCW06030000Z0EA)
R160  value 0  [FP-CRCW06031R50FKEAHP_0603-MFG]  (hidden comment: CRCW06030000Z0EA)
R200  Value1: 5%  ValueDisplayed: 1.8k  [0603]  (hidden comment: RC0603JR-071K8L)
R201  Value1: 5%  ValueDisplayed: 1.8k  [0603]  (hidden comment: RC0603JR-071K8L)
R300  value 1.5  [FP-CRCW080510R0JNEAHP_0805-MFG]  (hidden comment: CRCW08051R50FKEAHP)
TP1  5002  [Keystone5002]  (value not drawn)
TP2  5002  [Keystone5002]  (value not drawn)
TP3  5002  [Keystone5002]  (value not drawn)
TP4  5002  [Keystone5002]  (value not drawn)
TP5  5002  [Keystone5002]  (value not drawn)
TP6  5002  [Keystone5002]  (value not drawn)
TP7  5002  [Keystone5002]  (value not drawn)
TP8  5002  [Keystone5002]  (value not drawn)
TP9  5002  [Keystone5002]  (value not drawn)
TP10  5002  [Keystone5002]  (value not drawn)
TP11  5002  [Keystone5002]  (value not drawn)
TP12  5002  [Keystone5002]  (value not drawn)
TP13  5002  [Keystone5002]  (value not drawn)
TP14  5002  [Keystone5002]  (value not drawn)
TP15  5002  [Keystone5002]  (value not drawn)
TP16  5002  [Keystone5002]  (value not drawn)
TP17  5002  [Keystone5002]  (value not drawn)
TP18  5002  [Keystone5002]  (value not drawn)
TP19  5002  [Keystone5002]  (value not drawn)
TP20  5002  [Keystone5002]  (value not drawn)
TP21  5002  [Keystone5002]  (value not drawn)
TP22  5002  [Keystone5002]  (value not drawn)
TP23  5002  [Keystone5002]  (value not drawn)
TP24  5002  [Keystone5002]  (value not drawn)
TP25  5002  [Keystone5002]  (value not drawn)
TP26  5002  [Keystone5002]  (value not drawn)
TP27  5002  [Keystone5002]  (value not drawn)
TP28  5002  [Keystone5002]  (value not drawn)
TP29  5002  [Keystone5002]  (value not drawn)
TP30  5002  [Keystone5002]  (value not drawn)
TP31  5002  [Keystone5002]  (value not drawn)
TP32  5002  [Keystone5002]  (value not drawn)
TP33  5002  [Keystone5002]  (value not drawn)
TP34  5002  [Keystone5002]  (value not drawn)
TP35  5016  [Testpoint_Keystone_Compact]  (value not drawn)
TP36  5016  [Testpoint_Keystone_Compact]  (value not drawn)
TP37  5016  [Testpoint_Keystone_Compact]  (value not drawn)
TP38  5016  [Testpoint_Keystone_Compact]  (value not drawn)
TP39  5016  [Testpoint_Keystone_Compact]  (value not drawn)
TP40  5016  [Testpoint_Keystone_Compact]  (value not drawn)
TP42  5002  [Keystone5002]  (value not drawn)
TP43  5002  [Keystone5002]  (value not drawn)
TP44  5002  [Keystone5002]  (value not drawn)
TP47  5016  [Testpoint_Keystone_Compact]  (value not drawn)
U2  LT3010EMS8E#PBF  [FP-LT3010EMS8E-PBF_MSOP8-MFG]

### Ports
3V3_PULLUP, /CE, /INT, /PG, ACDRV, ACN, ACOV, ACP, ACUV, BAT, BAT_DRV, BAT_SRC, BTST1, BTST2, DRV_SUP, EXT_DRV, FB, FBG, FSW_SYNC, HIDRV1, HIDRV2, ICHG, ILIM_HIZ, LODRV1, LODRV2, MODE, PP5V, REGN, SCL, SDA, SRN, SRP, STAT1, STAT2, SW1, SW2, SYS, TS, VAC, VIN3V3

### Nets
PGND: C33.1 C48.2 C49.1 C201.2 C202.2 J4.6 J5.1 J6.1 J7.2 J7.3 J7.6(MNT_1) J7.7(MNT_2) J8.2 J8.3 JP3.2 JP4.2 JP7.2 JP8.2 JP9.2 JP10.2 JP11.2 JP13.2 R41.1 R49.1 R65.1 TP35.1 TP36.1 TP37.1 TP38.1 TP39.1 TP40.1 TP47.1 U2.4(GND) U2.9(GND)
3V3_PULLUP: C48.1 C50.1 R48.2 R69.1 TP32.1 U2.1(OUT) ; port 3V3_PULLUP
/CE: JP13.1 R56.1 TP21.1 ; port /CE
/INT: J8.5 JP14.2 TP30.1 ; port /INT
/PG: D6.1(K) J8.8 TP9.1 ; port /PG
ACDRV: TP4.1 ; port ACDRV
ACN: TP11.1 ; port ACN
ACOV: TP14.1 ; port ACOV
ACP: TP10.1 ; port ACP
ACUV: TP13.1 ; port ACUV
BAT: D9.2(ANODE) J7.1 TP3.1 ; port BAT
BAT_DRV: TP5.1 ; port BAT_DRV
BAT_SRC: TP6.1 ; port BAT_SRC
BTST1: TP26.1 ; port BTST1
BTST2: TP28.1 ; port BTST2
DRV_SUP: JP12.2 R300.2 TP15.1 ; port DRV_SUP
EXT_DRV: J6.2 R45.1 R68.2 ; port EXT_DRV
FB: TP24.1 ; port FB
FBG: TP42.1 ; port FBG
FSW_SYNC: JP8.1 R36.2 TP16.1 ; port FSW_SYNC
HIDRV1: TP25.1 ; port HIDRV1
HIDRV2: TP27.1 ; port HIDRV2
ICHG: JP3.1 R67.2 R201.2 TP17.1 ; port ICHG
ILIM_HIZ: JP11.1 R66.2 R200.2 TP7.1 ; port ILIM_HIZ
LODRV1: TP43.1 ; port LODRV1
LODRV2: TP44.1 ; port LODRV2
MODE: TP20.1 ; port MODE
PP5V: J8.1 R68.1 ; port PP5V
REGN: JP5.1 R160.1 TP1.1 ; port REGN
SCL: J4.9 J5.2 J8.4 R53.1 TP33.1 ; port SCL
SDA: J4.10 J5.3 J8.6 R54.1 TP34.1 ; port SDA
SRN: TP23.1 ; port SRN
SRP: TP22.1 ; port SRP
STAT1: JP15.2 TP29.1 ; port STAT1
STAT2: D5.1(K) TP31.1 ; port STAT2
SW1: TP18.1 ; port SW1
SW2: TP19.1 ; port SW2
SYS: TP2.1 ; port SYS
TS: JP6.1 JP7.1 R34.1 R65.2 TP8.1 ; port TS
VAC: D10.2(ANODE) J7.4 J7.5 TP12.1 ; port VAC
VIN3V3: J8.7 R50.2 R51.2 R52.2 R53.2 R54.2 R55.2 R56.2 R69.2 ; port VIN3V3
NetC33_2: C33.2 C49.2 R46.2 U2.5(~{SHDN}) U2.8(IN)
NetC50_2: C50.2 R48.1 R49.2 U2.2(ADJ)
NetC201_1: C201.1 R201.1
NetC202_1: C202.1 R200.1
NetD4_1: D4.1(K) JP15.1
NetD4_2: D4.2(A) R50.1
NetD5_2: D5.2(A) R51.1
NetD6_2: D6.2(A) R52.1
NetD9_1: D9.1(CATHODE) D10.1(CATHODE) JP16.2
NetJP4_1: JP4.1 R67.1
NetJP5_2: JP5.2 R34.2
NetJP6_2: JP6.2 R41.2
NetJP9_1: JP9.1 R36.1
NetJP10_1: JP10.1 R66.1
NetJP12_1: JP12.1 R160.2
NetJP12_3: JP12.3 R45.2 R300.1
NetJP14_1: JP14.1 R55.1
NetJP16_1: JP16.1 R46.1

Not connected (* = marked no-connect by the designer): J4 1* 2* 3* 4* 5 7* 8*; J5 4; U2 3(NC) 6(NC) 7(NC)

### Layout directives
net class HV: BAT, NetC33_2, NetD9_1, NetJP16_1, VAC

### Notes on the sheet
- (near C48) 3.3VDC@10mA
- VDC = 8V to 55V
- LDO to generate pull-up voltage
- NORMAL
- (near JP6) TS
- (near J6) EXT_DRV
- (near J4) USB2ANY Connector
- (near J5) BQStudio Connector

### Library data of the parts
C33 C49 = CMP-0093624-1: General Purpose Ceramic Capacitor, 1210, 1uF, 10%, X7R, 15%, 100V; Manufacturer: AVX; AEC Qualified: No; Cap_F: 1µF; Value: 1µF; SizeZ_mm: 2.79mm
C48 = CMP-0007728-2: CAP, CERM, 1 uF, 25 V, +/- 10%, X7R, 0805; Manufacturer: Kemet; TaMin_C: -55°C; Polarized: N; SizeAreaWB_mm2: 6.75; Value1: Unknown; U/M: EA; Value: 1uF; TaMax_C: 125°C; SizeZ_mm: 1.45; SizeX_mm: 2; SizeY_mm: 1.25; Cap_Case: 0805; SizeArea_mm2: 2.5; AEC Category: Q200
C50 = CMP-0006895-4: CAP, CERM, 220 pF, 50 V, +/- 10%, X7R, 0603; Manufacturer: Kemet; TaMin_C: -55°C; Polarized: N; SizeAreaWB_mm2: 4.68; Value1: Unknown; U/M: EA; Value: 220pF; TaMax_C: 125°C; SizeZ_mm: 1; SizeX_mm: 1.6; SizeY_mm: 0.8; SizeArea_mm2: 1.28; AEC Category: Q200
C201 C202 = CMP-0006862-5: CAP, CERM, 0.1 uF, 10 V, +/- 10%, X7R, 0603; Manufacturer: Kemet; TaMin_C: -55°C; Polarized: N; SizeAreaWB_mm2: 4.68; Value1: Unknown; U/M: EA; Value: 0.1uF; TaMax_C: 125°C; SizeZ_mm: 1; SizeX_mm: 1.6; SizeY_mm: 0.8; SizeArea_mm2: 1.28; AEC Category: Q200
D4-D6 = CMP-0002894-2: LED, Green, SMD; Manufacturer: Wurth Elektronik; Type: AlInGaP; Value2: 2V; Io_A: 20mA; Value1: W
D9 D10 = CMP-0096827-2: Diode Standard 100 V 1A Surface Mount DO-214AC (SMA); Manufacturer: Vishay; AEC Grade: Grade 0; AEC Category: Q101; Standoff Height: 0mm; Vr_V: 100V; SizeZ_mm: 2.29mm; AEC Qualified: Yes; Peak Reverse Current: 2uA; TJmax_C: 175°C; ValueDisplayed: 8.5pF; Max Surge Forward Current: 50A
J4 = CMP-0055448-2: Header (shrouded), 100mil, 5x2, High-Temperature, Gold, TH; Manufacturer: 3M; Green_Lifecycle: Active; Green_REACh: Passed
J5 = CMP-0055187-1: Header (friction lock), 100mil, 4x1, R/A, TH; Manufacturer: Molex; CNHeader: FALSE; Green_Lifecycle: Active; Green_REACh: Passed
J6 = CMP-0055341-2: Terminal Block, 3.5 mm, 2x1, Tin, TH; Manufacturer: Molex; CNHeader: FALSE; CT: TRUE; Green_Lifecycle: Not Set; Green_REACh: Incomplete
J7 = CMP-0097332-1: Conn Board to Board HDR 5 POS 3mm Solder RA SMD T/R; Manufacturer: KYOCERA AVX; AEC Qualified: No; Current_A: 5A; SizeZ_mm: 3.1mm; Voltage_V: 125V; ContactFinish: Gold,Nickel; Row_Count: 1; Standoff Height: 0.1mm; Conn Gender: Male; Conn Orientation: Horizontal
J8 = CMP-0075408-3: Header, 100mil, 4x2, Gold, TH; Manufacturer: Samtec; Gender: Male; Row_Count: 2; Cert_CSA: Y; Pitch_mm: 2.54; Green_REACh: Passed; Voltage_V: 550V; Current_A: 6.3A; Green_Lifecycle: Active; Cert_CULUS: N
JP3-JP11 JP16 = CMP-0002337-1: Header, 100mil, 2x1, Tin, TH; PartNumber: PEC02SAAN; Manufacturer: Sullins Connector Solutions; Pitch_mm: 2.54; Gender: Male; Shrouded: N; Row_Count: 1; Current_A: 3A; Voltage_V: 1.8kV; Cert_UL: Y; CNHeader: TRUE; CT: FALSE; Green_Lifecycle: Not Set; Green_REACh: Incomplete
JP12 = CMP-0002338-1: Header, 100mil, 3x1, Tin, TH; Manufacturer: Sullins Connector Solutions; Cert_UL: Y; CNHeader: TRUE; CT: FALSE; Current_A: 3A; Gender: Male; Green_Lifecycle: Not Set; Green_REACh: Incomplete; Pitch_mm: 2.54; Row_Count: 1; Shrouded: N; Voltage_V: 1.8kV
JP13-JP15 = CMP-0002337-1: as JP1 on sheet BMS042A_SCH_page1
R34 = CMP-0023199-5: RES, 5.23 k, 1%, 0.1 W, 0603; Manufacturer: Yageo; Power_W: 100mW; TempCo: 100 ppm/C; Value_Code: 5k23; Value: 5.23k; EIA_Code: E96; SizeX_mm: 1.6; SizeY_mm: 0.8; SizeZ_mm: 1; Value2: 0.1W; SizeArea_mm2: 1.28; AEC Qualified: N; VDC_V: 75V; AEC Category: Q200; SizeAreaWB_mm2: 4.68
R36 = CMP-0022038-4: RES, 133 k, 1%, 0.1 W, AEC-Q200 Grade 0, 0603; Manufacturer: Vishay-Dale; Power_W: 100mW; TempCo: 100 ppm/C; Value: 133k; EIA_Code: E96; SizeX_mm: 1.6; SizeY_mm: 0.8; SizeZ_mm: 1; Value2: 0.1W; SizeArea_mm2: 1.28; AEC Qualified: Y; VDC_V: 75V; AEC Category: Q200; AEC Grade: 0
R41 R53-R56 = CMP-0022746-5: RES, 10.0 k, 1%, 0.1 W, 0603; Manufacturer: Yageo; Power_W: 100mW; TempCo: 100 ppm/C; Value_Code: 10k0; Value: 10.0k; EIA_Code: E96; Res_ohm: 10k; SizeX_mm: 1.6; SizeY_mm: 0.8; SizeZ_mm: 1; Value2: 0.1W; SizeArea_mm2: 1.28; AEC Qualified: N; VDC_V: 75V; AEC Category: Q200; SizeAreaWB_mm2: 4.68
R45 = CMP-0092857-1: as R120 on sheet BMS042A_SCH_page1
R46 = CMP-0092853-1: Thick Film Resistors - SMD 3/4watt 20ohms 1% High Power AEC-Q200; Manufacturer: Vishay Dale; Part Number: CRCW12104R30FKEAHP; TempCo: 100ppm/°C; Power_W: 750mW; VDC_V: 200V; AEC Qualified: Yes; SizeZ_mm: 0.7mm; Res_ohm: 4.3; AEC Grade: Grade 0
R48 = CMP-0023140-4: RES, 499 k, 1%, 0.1 W, 0603; Manufacturer: Yageo; Power_W: 100mW; TempCo: 100 ppm/C; Value: 499k; EIA_Code: E96; SizeX_mm: 1.6; SizeY_mm: 0.8; SizeZ_mm: 1; Value2: 0.1W; SizeArea_mm2: 1.28; AEC Qualified: N; VDC_V: 75V; AEC Category: Q200; SizeAreaWB_mm2: 4.68
R49 = CMP-0093627-1: Thick Film Chip Resistors 0603 316kΩ 0.1W 1% 100ppm/°C; Manufacturer: Bourns; AEC Qualified: No; SizeZ_mm: 0.55mm; Power_W: 100mW; VDC_V: 75V
R50-R52 = CMP-0022984-5: RES, 2.21 k, 1%, 0.1 W, 0603; Manufacturer: Yageo; Power_W: 100mW; TempCo: 100 ppm/C; Value_Code: 2k21; Value: 2.21k; EIA_Code: E96; SizeX_mm: 1.6; SizeY_mm: 0.8; SizeZ_mm: 1; Value2: 0.1W; SizeArea_mm2: 1.28; AEC Qualified: N; VDC_V: 75V; AEC Category: Q200; SizeAreaWB_mm2: 4.68
R65 = CMP-0023018-5: RES, 30.1 k, 1%, 0.1 W, 0603; Manufacturer: Yageo; Power_W: 100mW; TempCo: 100 ppm/C; Value_Code: 30k1; Value: 30.1k; EIA_Code: E96; SizeX_mm: 1.6; SizeY_mm: 0.8; SizeZ_mm: 1; Value2: 0.1W; SizeArea_mm2: 1.28; AEC Qualified: N; VDC_V: 75V; AEC Category: Q200; SizeAreaWB_mm2: 4.68
R66 = CMP-0022990-5: RES, 2.49 k, 1%, 0.1 W, 0603; Manufacturer: Yageo; Power_W: 100mW; TempCo: 100 ppm/C; Value_Code: 2k49; Value: 2.49k; EIA_Code: E96; SizeX_mm: 1.6; SizeY_mm: 0.8; SizeZ_mm: 1; Value2: 0.1W; SizeArea_mm2: 1.28; AEC Qualified: N; VDC_V: 75V; AEC Category: Q200; SizeAreaWB_mm2: 4.68
R67 = CMP-0082533-1: RES, 4.99 k, 1%, 0.1 W, 0603; Manufacturer: Vishay-Dale; Power_W: 100mW; TempCo: 100 ppm/C; SizeAreaWB_mm2: 4.68; Value_Code: 4k99; Value: 4.99k; EIA_Code: E96; SizeX_mm: 1.6; SizeY_mm: 0.8; SizeZ_mm: 1; Value2: 0.1W; SizeArea_mm2: 1.28; AEC Qualified: N; VDC_V: 75V; AEC Category: Q200
R68 R69 R160 = CMP-0093629-1: as R3 on sheet BMS042A_SCH_page1
R200 R201 = CMP-0025898-5: RES, 1.8 k, 5%, 0.1 W, 0603; Manufacturer: Yageo; Power_W: 100mW; TempCo: 100 ppm/C; Value_Code: 1k80; Value: 1.8k; EIA_Code: E24; SizeX_mm: 1.6; SizeY_mm: 0.8; SizeZ_mm: 1; Value2: 0.1W; SizeArea_mm2: 1.28; AEC Qualified: N; VDC_V: 75V; AEC Category: Q200; SizeAreaWB_mm2: 4.68
R300 = CMP-0092857-1: Thick Film Resistors - SMD 1/2watt 1.5ohms 1% High Power AEC-Q200; Manufacturer: Vishay; Power_W: 500mW; SizeZ_mm: 0.6mm; AEC Qualified: Yes; TempCo: 200ppm/°C; VDC_V: 150V; Tolerance_%: 5%; AEC Grade: Grade 0
TP1-TP34 TP42-TP44 = CMP-0055139-1: as TP41 on sheet BMS042A_SCH_page1
TP35-TP40 TP47 = CMP-0055153-1: Test Point, Compact, SMT; Manufacturer: Keystone; CNHeader: FALSE; CT: TRUE; Green_Lifecycle: Active; Green_REACh: Passed
U2 = CMP-0093068-2: Linear Voltage Regulator IC Positive Adjustable 1 Output 50mA 8-MSOP-EP; PartNumber: LT3010EMS8E-PBF; Manufacturer: Analog Devices; Min Supply Voltage: 3V; Nominal Supply Current: 30-1800uA; Output Voltage: 1.275-60V; TJmax_C: +125°C; Max Supply Voltage: 80V; AEC Qualified: Yes; Standoff Height: 0.0508mm; SizeZ_mm: 1.1mm; AEC Grade: Grade 1; Dropout Voltage: 300mV; Number Of Outputs: 1; Output Type: AdjustableProgrammable

## Sheet BMS042A_SCH_powerpath_capacitors.SchDoc
size 431 x 279 mm; Date: Not shown in title block; ApprovedBy: Not shown in title block; CheckedBy: Not shown in title block; Author: Not shown in title block; CompanyName: Not shown in title block; Engineer: Not shown in title block; Organization: Not shown in title block; Address1: Not shown in title block; Address2: Not shown in title block; Address3: Not shown in title block; Address4: Not shown in title block; DocumentNumber: 2; Revision: Use project parameter SCH_Rev; SheetNumber: 2; SheetTotal: 4; PageSetup: Record=PageOptions¦CenterHorizontal=True¦CenterVertical=True¦PrintScale=1.00¦XCorrection=1.00¦YCorrection=1.00¦PrintKind=0¦BorderSize=5000000¦LeftOffset=0¦BottomOffset=0¦Orientation=2¦PaperLength=1000¦PaperWidth=1000¦Scale=100¦PaperSource=15¦PrintQuality=600¦MediaType=1¦DitherType=10¦PaperKind=Letter¦PrintScaleMode=1
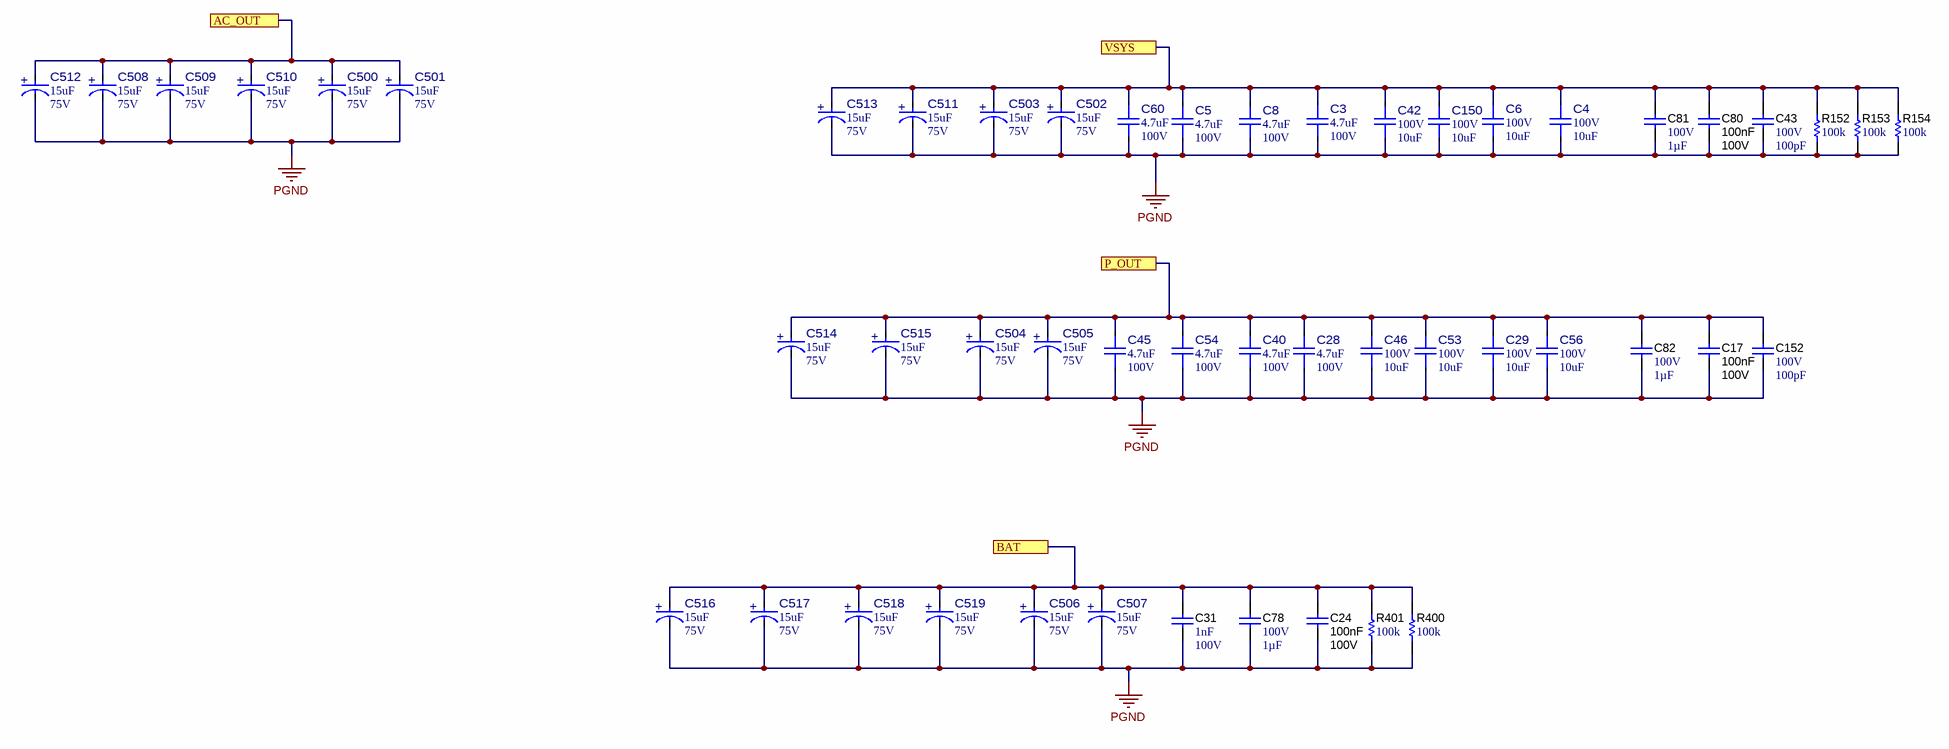
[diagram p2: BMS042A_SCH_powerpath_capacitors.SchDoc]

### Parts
C3  ValueDisplayed: 4.7uF  VDC_V: 100V  [FP-GCJ32DC72A475KE01L_1210-MFG]  (hidden comment: GCJ32DC72A475KE01L)
C4  VDC_V: 100V  ValueDisplayed: 10uF  [FP-C3225X7R2A106K250AC_1210-MFG]  (hidden comment: C3225X7R2A106K250AC)
C5  ValueDisplayed: 4.7uF  VDC_V: 100V  [FP-GCJ32DC72A475KE01L_1210-MFG]  (hidden comment: GCJ32DC72A475KE01L)
C6  VDC_V: 100V  ValueDisplayed: 10uF  [FP-C3225X7R2A106K250AC_1210-MFG]  (hidden comment: C3225X7R2A106K250AC)
C8  ValueDisplayed: 4.7uF  VDC_V: 100V  [FP-GCJ32DC72A475KE01L_1210-MFG]  (hidden comment: GCJ32DC72A475KE01L)
C17  Cap_F: 100nF  VDC_V: 100V  [0603L]  (hidden comment: HMK107B7104KAHT)
C24  Cap_F: 100nF  VDC_V: 100V  [0603_HV]  (hidden comment: HMK107B7104KAHT)
C28  ValueDisplayed: 4.7uF  VDC_V: 100V  [FP-GCJ32DC72A475KE01L_1210-MFG]  (hidden comment: GCJ32DC72A475KE01L)
C29  VDC_V: 100V  ValueDisplayed: 10uF  [FP-C3225X7R2A106K250AC_1210-MFG]  (hidden comment: C3225X7R2A106K250AC)
C31  Cap_F: 1nF  VDC_V: 100V  [0603]  (hidden comment: CGA3E2X7R2A102K080AA)
C40  ValueDisplayed: 4.7uF  VDC_V: 100V  [FP-GCJ32DC72A475KE01L_1210-MFG]  (hidden comment: GCJ32DC72A475KE01L)
C42  VDC_V: 100V  ValueDisplayed: 10uF  [FP-C3225X7R2A106K250AC_1210-MFG]  (hidden comment: C3225X7R2A106K250AC)
C43  VDC_V: 100V  ValueDisplayed: 100pF  [0603]  (hidden comment: CGA3E2C0G2A101J080AA)
C45  ValueDisplayed: 4.7uF  VDC_V: 100V  [FP-GCJ32DC72A475KE01L_1210-MFG]  (hidden comment: GCJ32DC72A475KE01L)
C46  VDC_V: 100V  ValueDisplayed: 10uF  [FP-C3225X7R2A106K250AC_1210-MFG]  (hidden comment: C3225X7R2A106K250AC)
C53  VDC_V: 100V  ValueDisplayed: 10uF  [FP-C3225X7R2A106K250AC_1210-MFG]  (hidden comment: C3225X7R2A106K250AC)
C54  ValueDisplayed: 4.7uF  VDC_V: 100V  [FP-GCJ32DC72A475KE01L_1210-MFG]  (hidden comment: GCJ32DC72A475KE01L)
C56  VDC_V: 100V  ValueDisplayed: 10uF  [FP-C3225X7R2A106K250AC_1210-MFG]  (hidden comment: C3225X7R2A106K250AC)
C60  ValueDisplayed: 4.7uF  VDC_V: 100V  [FP-GCJ32DC72A475KE01L_1210-MFG]  (hidden comment: GCJ32DC72A475KE01L)
C78  VDC_V: 100V  Cap_F: 1µF  [0805_150]  (hidden comment: 08051C105K4Z2A)
C80  Cap_F: 100nF  VDC_V: 100V  [0603L]  (hidden comment: HMK107B7104KAHT)
C81  VDC_V: 100V  Cap_F: 1µF  [0805_150]  (hidden comment: 08051C105K4Z2A)
C82  VDC_V: 100V  Cap_F: 1µF  [0805_150]  (hidden comment: 08051C105K4Z2A)
C150  VDC_V: 100V  ValueDisplayed: 10uF  [FP-C3225X7R2A106K250AC_1210-MFG]  (hidden comment: C3225X7R2A106K250AC)
C152  VDC_V: 100V  ValueDisplayed: 100pF  [0603]  (hidden comment: CGA3E2C0G2A101J080AA)
C500  ValueDisplayed: 15uF  VDC_V: 75V  [FP-T521X156M075ATE035_2917-MFG]  (hidden comment: T521X156M075ATE035)
C501  ValueDisplayed: 15uF  VDC_V: 75V  [FP-T521X156M075ATE035_2917-MFG]  (hidden comment: T521X156M075ATE035)
C502  ValueDisplayed: 15uF  VDC_V: 75V  [FP-T521X156M075ATE035_2917-MFG]  (hidden comment: T521X156M075ATE035)
C503  ValueDisplayed: 15uF  VDC_V: 75V  [FP-T521X156M075ATE035_2917-MFG]  (hidden comment: T521X156M075ATE035)
C504  ValueDisplayed: 15uF  VDC_V: 75V  [FP-T521X156M075ATE035_2917-MFG]  (hidden comment: T521X156M075ATE035)
C505  ValueDisplayed: 15uF  VDC_V: 75V  [FP-T521X156M075ATE035_2917-MFG]  (hidden comment: T521X156M075ATE035)
C506  ValueDisplayed: 15uF  VDC_V: 75V  [FP-T521X156M075ATE035_2917-MFG]  (hidden comment: T521X156M075ATE035)
C507  ValueDisplayed: 15uF  VDC_V: 75V  [FP-T521X156M075ATE035_2917-MFG]  (hidden comment: T521X156M075ATE035)
C508  ValueDisplayed: 15uF  VDC_V: 75V  [FP-T521X156M075ATE035_2917-MFG]  (hidden comment: T521X156M075ATE035)
C509  ValueDisplayed: 15uF  VDC_V: 75V  [FP-T521X156M075ATE035_2917-MFG]  (hidden comment: T521X156M075ATE035)
C510  ValueDisplayed: 15uF  VDC_V: 75V  [FP-T521X156M075ATE035_2917-MFG]  (hidden comment: T521X156M075ATE035)
C511  ValueDisplayed: 15uF  VDC_V: 75V  [FP-T521X156M075ATE035_2917-MFG]  (hidden comment: T521X156M075ATE035)
C512  ValueDisplayed: 15uF  VDC_V: 75V  [FP-T521X156M075ATE035_2917-MFG]  (hidden comment: T521X156M075ATE035)
C513  ValueDisplayed: 15uF  VDC_V: 75V  [FP-T521X156M075ATE035_2917-MFG]  (hidden comment: T521X156M075ATE035)
C514  ValueDisplayed: 15uF  VDC_V: 75V  [FP-T521X156M075ATE035_2917-MFG]  (hidden comment: T521X156M075ATE035)
C515  ValueDisplayed: 15uF  VDC_V: 75V  [FP-T521X156M075ATE035_2917-MFG]  (hidden comment: T521X156M075ATE035)
C516  ValueDisplayed: 15uF  VDC_V: 75V  [FP-T521X156M075ATE035_2917-MFG]  (hidden comment: T521X156M075ATE035)
C517  ValueDisplayed: 15uF  VDC_V: 75V  [FP-T521X156M075ATE035_2917-MFG]  (hidden comment: T521X156M075ATE035)
C518  ValueDisplayed: 15uF  VDC_V: 75V  [FP-T521X156M075ATE035_2917-MFG]  (hidden comment: T521X156M075ATE035)
C519  ValueDisplayed: 15uF  VDC_V: 75V  [FP-T521X156M075ATE035_2917-MFG]  (hidden comment: T521X156M075ATE035)
R152  ValueDisplayed: 100k  [1210]  (hidden comment: RC1210JR-07100KL)
R153  ValueDisplayed: 100k  [1210]  (hidden comment: RC1210JR-07100KL)
R154  ValueDisplayed: 100k  [1210]  (hidden comment: RC1210JR-07100KL)
R400  ValueDisplayed: 100k  [1210]  (hidden comment: RC1210JR-07100KL)
R401  ValueDisplayed: 100k  [1210]  (hidden comment: RC1210JR-07100KL)

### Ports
AC_OUT, BAT, P_OUT, VSYS

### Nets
PGND: C3.2 C4.2 C5.1 C6.2 C8.1 C17.2 C24.2 C28.1 C29.1 C31.2 C40.1 C42.1 C43.2 C45.1 C46.1 C53.1 C54.1 C56.1 C60.2 C78.2 C80.2 C81.2 C82.2 C150.1 C152.2 C500.1(CATHODE) C501.1(CATHODE) C502.1(CATHODE) C503.1(CATHODE) C504.1(CATHODE) C505.1(CATHODE) C506.1(CATHODE) C507.1(CATHODE) C508.1(CATHODE) C509.1(CATHODE) C510.1(CATHODE) C511.1(CATHODE) C512.1(CATHODE) C513.1(CATHODE) C514.1(CATHODE) C515.1(CATHODE) C516.1(CATHODE) C517.1(CATHODE) C518.1(CATHODE) C519.1(CATHODE) R152.1 R153.1 R154.1 R400.1 R401.1
AC_OUT: C500.2(ANODE) C501.2(ANODE) C508.2(ANODE) C509.2(ANODE) C510.2(ANODE) C512.2(ANODE) ; port AC_OUT
BAT: C24.1 C31.1 C78.1 C506.2(ANODE) C507.2(ANODE) C516.2(ANODE) C517.2(ANODE) C518.2(ANODE) C519.2(ANODE) R400.2 R401.2 ; port BAT
P_OUT: C17.1 C28.2 C29.2 C40.2 C45.2 C46.2 C53.2 C54.2 C56.2 C82.1 C152.1 C504.2(ANODE) C505.2(ANODE) C514.2(ANODE) C515.2(ANODE) ; port P_OUT
VSYS: C3.1 C4.1 C5.2 C6.1 C8.2 C42.2 C43.1 C60.1 C80.1 C81.1 C150.2 C502.2(ANODE) C503.2(ANODE) C511.2(ANODE) C513.2(ANODE) R152.2 R153.2 R154.2 ; port VSYS

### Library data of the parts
C3 C5 C8 C28 C40 C45 C54 C60 = CMP-0093675-1: as C2 on sheet BMS042A_SCH_page1
C4 C6 C29 C42 C46 C53 C56 C150 = CMP-0096021-1: 10 µF ±10% 100V Ceramic Capacitor X7R 1210 (3225 Metric); Manufacturer: TDK; Cap_F: 10µF; AEC Qualified: No; Value: 10µF; SizeZ_mm: 2.85mm; TempCo: 15%
C17 C24 C80 = CMP-0081011-1: as C10 on sheet BMS042A_SCH_page1
C31 = CMP-0007081-4: as C151 on sheet BMS042A_SCH_page1
C43 C152 = CMP-0007237-3: Multilayer Ceramic Capacitors MLCC - SMD/SMT CGA 0603 100V 100pF C0G 5% AEC-Q200; Manufacturer: TDK; TaMin_C: -55°C; Polarized: N; TempCo: C0G/NP0; SizeAreaWB_mm2: 4.68; Value1: Unknown; U/M: EA; TaMax_C: 125°C; SizeZ_mm: 1; SizeX_mm: 1.6; SizeY_mm: 0.8; SizeArea_mm2: 1.28; AEC Category: Q200
C78 C81 C82 = CMP-0861070-1: as C16 on sheet BMS042A_SCH_page1
C500-C519 = CMP-0096796-1: Cap Tant Polymer 15uF 75VDC X CASE 20% (7.3 X 4.3 X 4mm) SMD 7343-43 0.035 Ohm 125C T/R; Manufacturer: KEMET; Esr: 35m; SizeZ_mm: 4.3mm; Life: 2000Hours; Standoff Height: 0mm; Leakage Current: 112.5uA; AEC Qualified: No; Dissipation Factor: 10%; Value: 15µF; IRMS_A: 3.38A
R152-R154 R400 R401 = CMP-0083440-1: as R151 on sheet BMS042A_SCH_page1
